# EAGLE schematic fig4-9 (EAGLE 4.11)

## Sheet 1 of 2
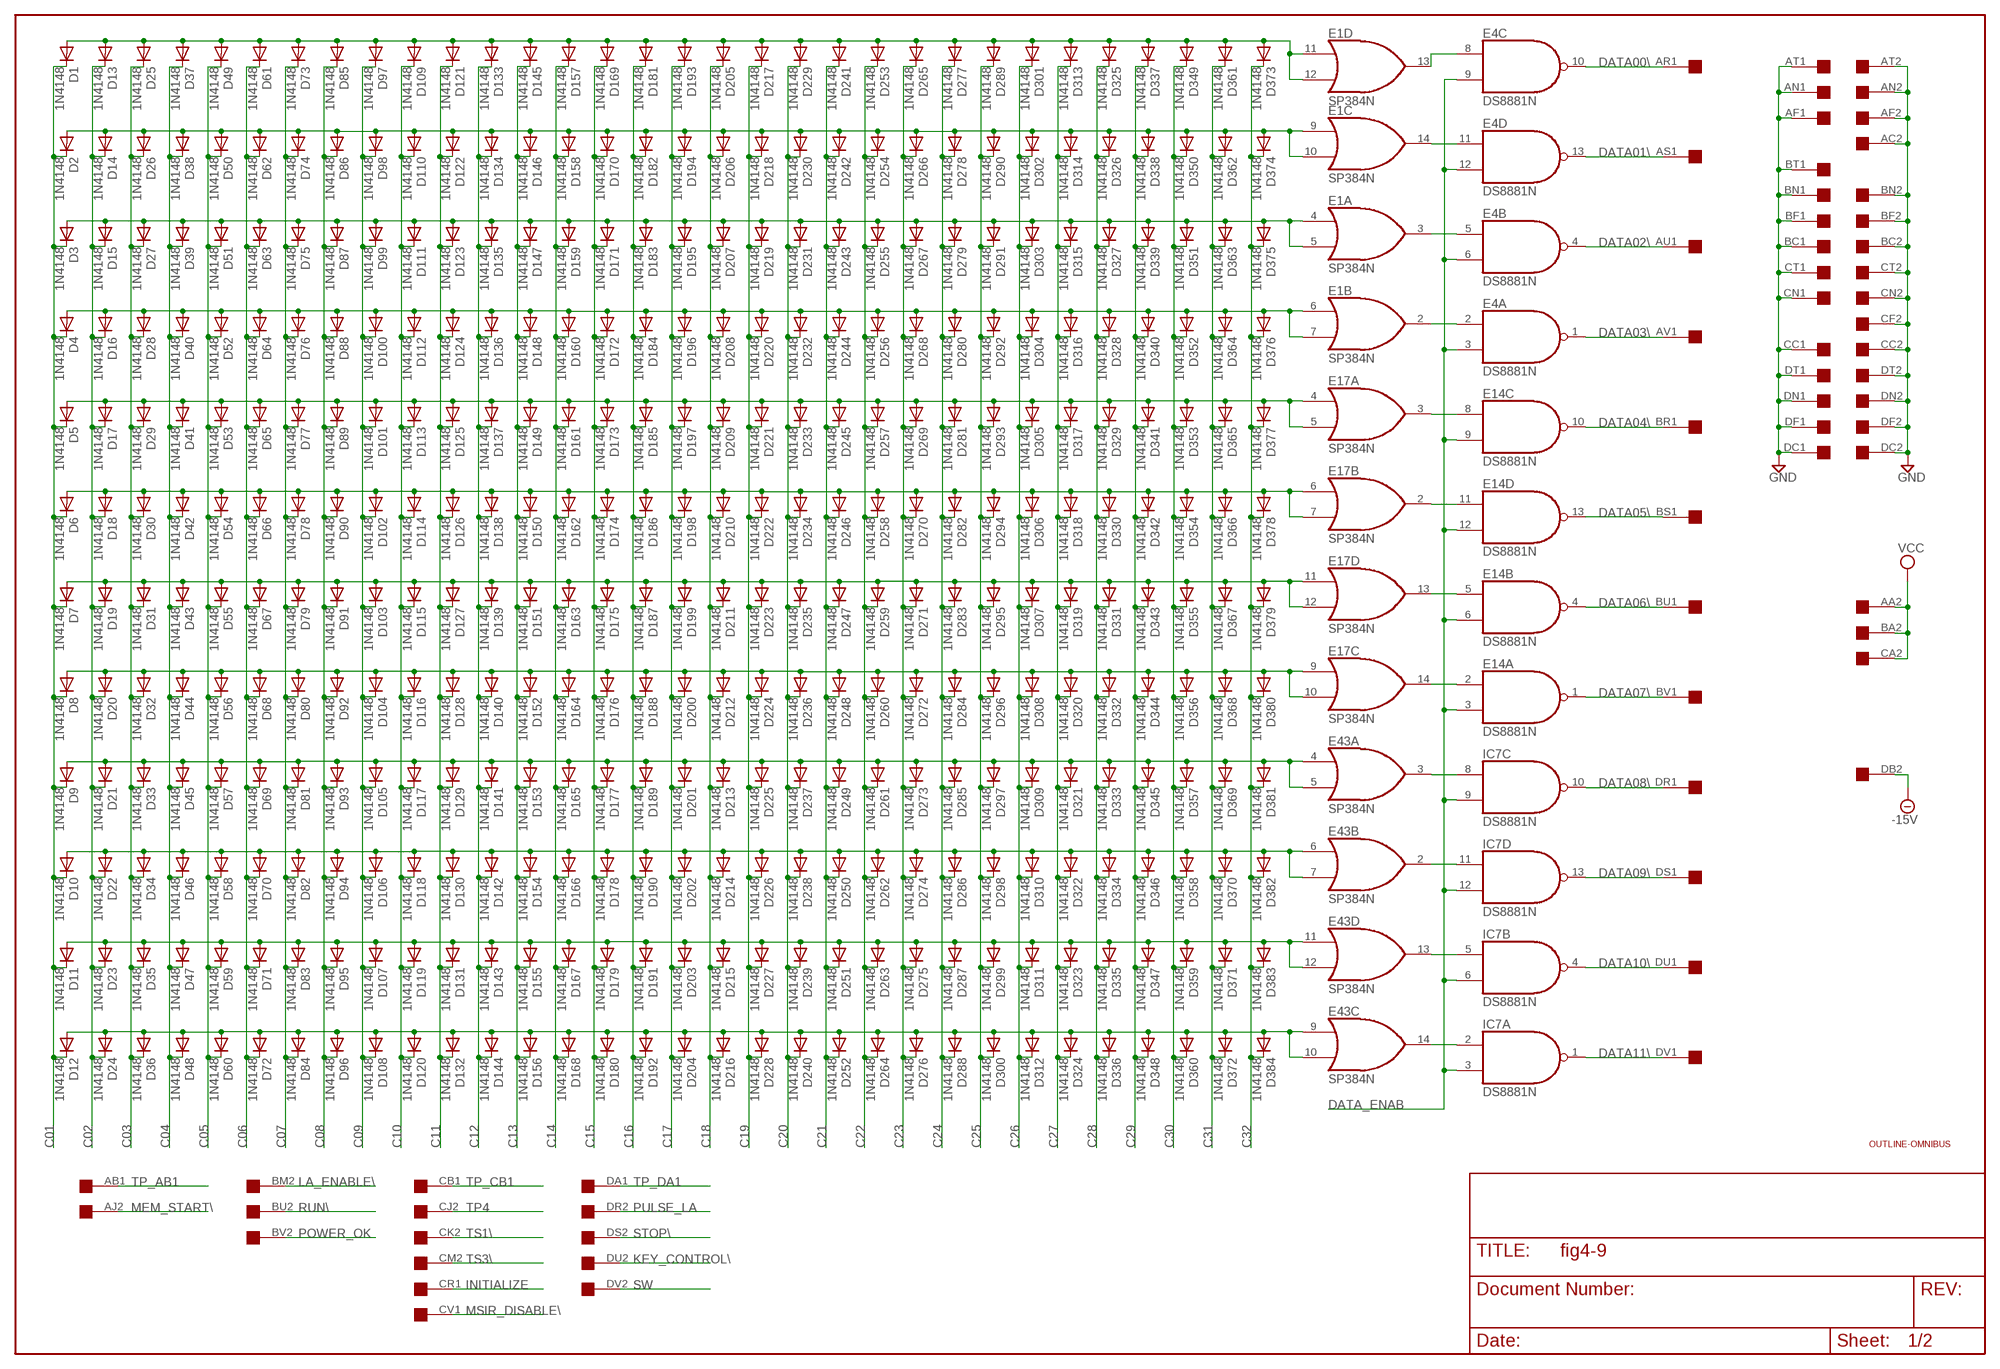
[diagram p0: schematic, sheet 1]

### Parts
D1  1N4148  [DO35-10]
D2  1N4148  [DO35-10]
D3  1N4148  [DO35-10]
D4  1N4148  [DO35-10]
D5  1N4148  [DO35-10]
D6  1N4148  [DO35-10]
D7  1N4148  [DO35-10]
D8  1N4148  [DO35-10]
D9  1N4148  [DO35-10]
D10  1N4148  [DO35-10]
D11  1N4148  [DO35-10]
D12  1N4148  [DO35-10]
D13  1N4148  [DO35-10]
D14  1N4148  [DO35-10]
D15  1N4148  [DO35-10]
D16  1N4148  [DO35-10]
D17  1N4148  [DO35-10]
D18  1N4148  [DO35-10]
D19  1N4148  [DO35-10]
D20  1N4148  [DO35-10]
D21  1N4148  [DO35-10]
D22  1N4148  [DO35-10]
D23  1N4148  [DO35-10]
D24  1N4148  [DO35-10]
D25  1N4148  [DO35-10]
D26  1N4148  [DO35-10]
D27  1N4148  [DO35-10]
D28  1N4148  [DO35-10]
D29  1N4148  [DO35-10]
D30  1N4148  [DO35-10]
D31  1N4148  [DO35-10]
D32  1N4148  [DO35-10]
D33  1N4148  [DO35-10]
D34  1N4148  [DO35-10]
D35  1N4148  [DO35-10]
D36  1N4148  [DO35-10]
D37  1N4148  [DO35-10]
D38  1N4148  [DO35-10]
D39  1N4148  [DO35-10]
D40  1N4148  [DO35-10]
D41  1N4148  [DO35-10]
D42  1N4148  [DO35-10]
D43  1N4148  [DO35-10]
D44  1N4148  [DO35-10]
D45  1N4148  [DO35-10]
D46  1N4148  [DO35-10]
D47  1N4148  [DO35-10]
D48  1N4148  [DO35-10]
D49  1N4148  [DO35-10]
D50  1N4148  [DO35-10]
D51  1N4148  [DO35-10]
D52  1N4148  [DO35-10]
D53  1N4148  [DO35-10]
D54  1N4148  [DO35-10]
D55  1N4148  [DO35-10]
D56  1N4148  [DO35-10]
D57  1N4148  [DO35-10]
D58  1N4148  [DO35-10]
D59  1N4148  [DO35-10]
D60  1N4148  [DO35-10]
D61  1N4148  [DO35-10]
D62  1N4148  [DO35-10]
D63  1N4148  [DO35-10]
D64  1N4148  [DO35-10]
D65  1N4148  [DO35-10]
D66  1N4148  [DO35-10]
D67  1N4148  [DO35-10]
D68  1N4148  [DO35-10]
D69  1N4148  [DO35-10]
D70  1N4148  [DO35-10]
D71  1N4148  [DO35-10]
D72  1N4148  [DO35-10]
D73  1N4148  [DO35-10]
D74  1N4148  [DO35-10]
D75  1N4148  [DO35-10]
D76  1N4148  [DO35-10]
D77  1N4148  [DO35-10]
D78  1N4148  [DO35-10]
D79  1N4148  [DO35-10]
D80  1N4148  [DO35-10]
D81  1N4148  [DO35-10]
D82  1N4148  [DO35-10]
D83  1N4148  [DO35-10]
D84  1N4148  [DO35-10]
D85  1N4148  [DO35-10]
D86  1N4148  [DO35-10]
D87  1N4148  [DO35-10]
D88  1N4148  [DO35-10]
D89  1N4148  [DO35-10]
D90  1N4148  [DO35-10]
D91  1N4148  [DO35-10]
D92  1N4148  [DO35-10]
D93  1N4148  [DO35-10]
D94  1N4148  [DO35-10]
D95  1N4148  [DO35-10]
D96  1N4148  [DO35-10]
D97  1N4148  [DO35-10]
D98  1N4148  [DO35-10]
D99  1N4148  [DO35-10]
D100  1N4148  [DO35-10]
D101  1N4148  [DO35-10]
D102  1N4148  [DO35-10]
D103  1N4148  [DO35-10]
D104  1N4148  [DO35-10]
D105  1N4148  [DO35-10]
D106  1N4148  [DO35-10]
D107  1N4148  [DO35-10]
D108  1N4148  [DO35-10]
D109  1N4148  [DO35-10]
D110  1N4148  [DO35-10]
D111  1N4148  [DO35-10]
D112  1N4148  [DO35-10]
D113  1N4148  [DO35-10]
D114  1N4148  [DO35-10]
D115  1N4148  [DO35-10]
D116  1N4148  [DO35-10]
D117  1N4148  [DO35-10]
D118  1N4148  [DO35-10]
D119  1N4148  [DO35-10]
D120  1N4148  [DO35-10]
D121  1N4148  [DO35-10]
D122  1N4148  [DO35-10]
D123  1N4148  [DO35-10]
D124  1N4148  [DO35-10]
D125  1N4148  [DO35-10]
D126  1N4148  [DO35-10]
D127  1N4148  [DO35-10]
D128  1N4148  [DO35-10]
D129  1N4148  [DO35-10]
D130  1N4148  [DO35-10]
D131  1N4148  [DO35-10]
D132  1N4148  [DO35-10]
D133  1N4148  [DO35-10]
D134  1N4148  [DO35-10]
D135  1N4148  [DO35-10]
D136  1N4148  [DO35-10]
D137  1N4148  [DO35-10]
D138  1N4148  [DO35-10]
D139  1N4148  [DO35-10]
D140  1N4148  [DO35-10]
D141  1N4148  [DO35-10]
D142  1N4148  [DO35-10]
D143  1N4148  [DO35-10]
D144  1N4148  [DO35-10]
D145  1N4148  [DO35-10]
D146  1N4148  [DO35-10]
D147  1N4148  [DO35-10]
D148  1N4148  [DO35-10]
D149  1N4148  [DO35-10]
D150  1N4148  [DO35-10]
D151  1N4148  [DO35-10]
D152  1N4148  [DO35-10]
D153  1N4148  [DO35-10]
D154  1N4148  [DO35-10]
D155  1N4148  [DO35-10]
D156  1N4148  [DO35-10]
D157  1N4148  [DO35-10]
D158  1N4148  [DO35-10]
D159  1N4148  [DO35-10]
D160  1N4148  [DO35-10]
D161  1N4148  [DO35-10]
D162  1N4148  [DO35-10]
D163  1N4148  [DO35-10]
D164  1N4148  [DO35-10]
D165  1N4148  [DO35-10]
D166  1N4148  [DO35-10]
D167  1N4148  [DO35-10]
D168  1N4148  [DO35-10]
D169  1N4148  [DO35-10]
D170  1N4148  [DO35-10]
D171  1N4148  [DO35-10]
D172  1N4148  [DO35-10]
D173  1N4148  [DO35-10]
D174  1N4148  [DO35-10]
D175  1N4148  [DO35-10]
D176  1N4148  [DO35-10]
D177  1N4148  [DO35-10]
D178  1N4148  [DO35-10]
D179  1N4148  [DO35-10]
D180  1N4148  [DO35-10]
D181  1N4148  [DO35-10]
D182  1N4148  [DO35-10]
D183  1N4148  [DO35-10]
D184  1N4148  [DO35-10]
D185  1N4148  [DO35-10]
D186  1N4148  [DO35-10]
D187  1N4148  [DO35-10]
D188  1N4148  [DO35-10]
D189  1N4148  [DO35-10]
D190  1N4148  [DO35-10]
D191  1N4148  [DO35-10]
D192  1N4148  [DO35-10]
D193  1N4148  [DO35-10]
D194  1N4148  [DO35-10]
D195  1N4148  [DO35-10]
D196  1N4148  [DO35-10]
D197  1N4148  [DO35-10]
D198  1N4148  [DO35-10]
D199  1N4148  [DO35-10]
D200  1N4148  [DO35-10]
D201  1N4148  [DO35-10]
D202  1N4148  [DO35-10]
D203  1N4148  [DO35-10]
D204  1N4148  [DO35-10]
D205  1N4148  [DO35-10]
D206  1N4148  [DO35-10]
D207  1N4148  [DO35-10]
D208  1N4148  [DO35-10]
D209  1N4148  [DO35-10]
D210  1N4148  [DO35-10]
D211  1N4148  [DO35-10]
D212  1N4148  [DO35-10]
D213  1N4148  [DO35-10]
D214  1N4148  [DO35-10]
D215  1N4148  [DO35-10]
D216  1N4148  [DO35-10]
D217  1N4148  [DO35-10]
D218  1N4148  [DO35-10]
D219  1N4148  [DO35-10]
D220  1N4148  [DO35-10]
D221  1N4148  [DO35-10]
D222  1N4148  [DO35-10]
D223  1N4148  [DO35-10]
D224  1N4148  [DO35-10]
D225  1N4148  [DO35-10]
D226  1N4148  [DO35-10]
D227  1N4148  [DO35-10]
D228  1N4148  [DO35-10]
D229  1N4148  [DO35-10]
D230  1N4148  [DO35-10]
D231  1N4148  [DO35-10]
D232  1N4148  [DO35-10]
D233  1N4148  [DO35-10]
D234  1N4148  [DO35-10]
D235  1N4148  [DO35-10]
D236  1N4148  [DO35-10]
D237  1N4148  [DO35-10]
D238  1N4148  [DO35-10]
D239  1N4148  [DO35-10]
D240  1N4148  [DO35-10]
D241  1N4148  [DO35-10]
D242  1N4148  [DO35-10]
D243  1N4148  [DO35-10]
D244  1N4148  [DO35-10]
D245  1N4148  [DO35-10]
D246  1N4148  [DO35-10]
D247  1N4148  [DO35-10]
D248  1N4148  [DO35-10]
D249  1N4148  [DO35-10]
D250  1N4148  [DO35-10]
D251  1N4148  [DO35-10]
D252  1N4148  [DO35-10]
D253  1N4148  [DO35-10]
D254  1N4148  [DO35-10]
D255  1N4148  [DO35-10]
D256  1N4148  [DO35-10]
D257  1N4148  [DO35-10]
D258  1N4148  [DO35-10]
D259  1N4148  [DO35-10]
D260  1N4148  [DO35-10]
D261  1N4148  [DO35-10]
D262  1N4148  [DO35-10]
D263  1N4148  [DO35-10]
D264  1N4148  [DO35-10]
D265  1N4148  [DO35-10]
D266  1N4148  [DO35-10]
D267  1N4148  [DO35-10]
D268  1N4148  [DO35-10]
D269  1N4148  [DO35-10]
D270  1N4148  [DO35-10]
D271  1N4148  [DO35-10]
D272  1N4148  [DO35-10]
D273  1N4148  [DO35-10]
D274  1N4148  [DO35-10]
D275  1N4148  [DO35-10]
D276  1N4148  [DO35-10]
D277  1N4148  [DO35-10]
D278  1N4148  [DO35-10]
D279  1N4148  [DO35-10]
D280  1N4148  [DO35-10]
D281  1N4148  [DO35-10]
D282  1N4148  [DO35-10]
D283  1N4148  [DO35-10]
D284  1N4148  [DO35-10]
D285  1N4148  [DO35-10]
D286  1N4148  [DO35-10]
D287  1N4148  [DO35-10]
D288  1N4148  [DO35-10]
D289  1N4148  [DO35-10]
D290  1N4148  [DO35-10]
D291  1N4148  [DO35-10]
D292  1N4148  [DO35-10]
D293  1N4148  [DO35-10]
D294  1N4148  [DO35-10]
D295  1N4148  [DO35-10]
D296  1N4148  [DO35-10]
D297  1N4148  [DO35-10]
D298  1N4148  [DO35-10]
D299  1N4148  [DO35-10]
D300  1N4148  [DO35-10]
D301  1N4148  [DO35-10]
D302  1N4148  [DO35-10]
D303  1N4148  [DO35-10]
D304  1N4148  [DO35-10]
D305  1N4148  [DO35-10]
D306  1N4148  [DO35-10]
D307  1N4148  [DO35-10]
D308  1N4148  [DO35-10]
D309  1N4148  [DO35-10]
D310  1N4148  [DO35-10]
D311  1N4148  [DO35-10]
D312  1N4148  [DO35-10]
D313  1N4148  [DO35-10]
D314  1N4148  [DO35-10]
D315  1N4148  [DO35-10]
D316  1N4148  [DO35-10]
D317  1N4148  [DO35-10]
D318  1N4148  [DO35-10]
D319  1N4148  [DO35-10]
D320  1N4148  [DO35-10]
D321  1N4148  [DO35-10]
D322  1N4148  [DO35-10]
D323  1N4148  [DO35-10]
D324  1N4148  [DO35-10]
D325  1N4148  [DO35-10]
D326  1N4148  [DO35-10]
D327  1N4148  [DO35-10]
D328  1N4148  [DO35-10]
D329  1N4148  [DO35-10]
D330  1N4148  [DO35-10]
D331  1N4148  [DO35-10]
D332  1N4148  [DO35-10]
D333  1N4148  [DO35-10]
D334  1N4148  [DO35-10]
D335  1N4148  [DO35-10]
D336  1N4148  [DO35-10]
D337  1N4148  [DO35-10]
D338  1N4148  [DO35-10]
D339  1N4148  [DO35-10]
D340  1N4148  [DO35-10]
D341  1N4148  [DO35-10]
D342  1N4148  [DO35-10]
D343  1N4148  [DO35-10]
D344  1N4148  [DO35-10]
D345  1N4148  [DO35-10]
D346  1N4148  [DO35-10]
D347  1N4148  [DO35-10]
D348  1N4148  [DO35-10]
D349  1N4148  [DO35-10]
D350  1N4148  [DO35-10]
D351  1N4148  [DO35-10]
D352  1N4148  [DO35-10]
D353  1N4148  [DO35-10]
D354  1N4148  [DO35-10]
D355  1N4148  [DO35-10]
D356  1N4148  [DO35-10]
D357  1N4148  [DO35-10]
D358  1N4148  [DO35-10]
D359  1N4148  [DO35-10]
D360  1N4148  [DO35-10]
D361  1N4148  [DO35-10]
D362  1N4148  [DO35-10]
D363  1N4148  [DO35-10]
D364  1N4148  [DO35-10]
D365  1N4148  [DO35-10]
D366  1N4148  [DO35-10]
D367  1N4148  [DO35-10]
D368  1N4148  [DO35-10]
D369  1N4148  [DO35-10]
D370  1N4148  [DO35-10]
D371  1N4148  [DO35-10]
D372  1N4148  [DO35-10]
D373  1N4148  [DO35-10]
D374  1N4148  [DO35-10]
D375  1N4148  [DO35-10]
D376  1N4148  [DO35-10]
D377  1N4148  [DO35-10]
D378  1N4148  [DO35-10]
D379  1N4148  [DO35-10]
D380  1N4148  [DO35-10]
D381  1N4148  [DO35-10]
D382  1N4148  [DO35-10]
D383  1N4148  [DO35-10]
D384  1N4148  [DO35-10]
E1  SP384N  [DIL14]
E4  DS8881N  [DIL14]
E14  DS8881N  [DIL14]
E17  SP384N  [DIL14]
E43  SP384N  [DIL14]
IC7  DS8881N  [DIL14]
U$1  OUTLINE-OMNIBUS  [OMNIBUS]
U$2  QUAD  [EDGE-CON8]

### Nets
-15V: U$2.DB2
C01: D1.C D2.C D3.C D4.C D5.C D6.C D7.C D8.C D9.C D10.C D11.C D12.C ; also sheet 2
C02: D13.C D14.C D15.C D16.C D17.C D18.C D19.C D20.C D21.C D22.C D23.C D24.C ; also sheet 2
C03: D25.C D26.C D27.C D28.C D29.C D30.C D31.C D32.C D33.C D34.C D35.C D36.C ; also sheet 2
C04: D37.C D38.C D39.C D40.C D41.C D42.C D43.C D44.C D45.C D46.C D47.C D48.C ; also sheet 2
C05: D49.C D50.C D51.C D52.C D53.C D54.C D55.C D56.C D57.C D58.C D59.C D60.C ; also sheet 2
C06: D61.C D62.C D63.C D64.C D65.C D66.C D67.C D68.C D69.C D70.C D71.C D72.C ; also sheet 2
C07: D73.C D74.C D75.C D76.C D77.C D78.C D79.C D80.C D81.C D82.C D83.C D84.C ; also sheet 2
C08: D85.C D86.C D87.C D88.C D89.C D90.C D91.C D92.C D93.C D94.C D95.C D96.C ; also sheet 2
C09: D97.C D98.C D99.C D100.C D101.C D102.C D103.C D104.C D105.C D106.C D107.C D108.C ; also sheet 2
C10: D109.C D110.C D111.C D112.C D113.C D114.C D115.C D116.C D117.C D118.C D119.C D120.C ; also sheet 2
C11: D121.C D122.C D123.C D124.C D125.C D126.C D127.C D128.C D129.C D130.C D131.C D132.C ; also sheet 2
C12: D133.C D134.C D135.C D136.C D137.C D138.C D139.C D140.C D141.C D142.C D143.C D144.C ; also sheet 2
C13: D145.C D146.C D147.C D148.C D149.C D150.C D151.C D152.C D153.C D154.C D155.C D156.C ; also sheet 2
C14: D157.C D158.C D159.C D160.C D161.C D162.C D163.C D164.C D165.C D166.C D167.C D168.C ; also sheet 2
C15: D169.C D170.C D171.C D172.C D173.C D174.C D175.C D176.C D177.C D178.C D179.C D180.C ; also sheet 2
C16: D181.C D182.C D183.C D184.C D185.C D186.C D187.C D188.C D189.C D190.C D191.C D192.C ; also sheet 2
C17: D193.C D194.C D195.C D196.C D197.C D198.C D199.C D200.C D201.C D202.C D203.C D204.C ; also sheet 2
C18: D205.C D206.C D207.C D208.C D209.C D210.C D211.C D212.C D213.C D214.C D215.C D216.C ; also sheet 2
C19: D217.C D218.C D219.C D220.C D221.C D222.C D223.C D224.C D225.C D226.C D227.C D228.C ; also sheet 2
C20: D229.C D230.C D231.C D232.C D233.C D234.C D235.C D236.C D237.C D238.C D239.C D240.C ; also sheet 2
C21: D241.C D242.C D243.C D244.C D245.C D246.C D247.C D248.C D249.C D250.C D251.C D252.C ; also sheet 2
C22: D253.C D254.C D255.C D256.C D257.C D258.C D259.C D260.C D261.C D262.C D263.C D264.C ; also sheet 2
C23: D265.C D266.C D267.C D268.C D269.C D270.C D271.C D272.C D273.C D274.C D275.C D276.C ; also sheet 2
C24: D277.C D278.C D279.C D280.C D281.C D282.C D283.C D284.C D285.C D286.C D287.C D288.C ; also sheet 2
C25: D289.C D290.C D291.C D292.C D293.C D294.C D295.C D296.C D297.C D298.C D299.C D300.C ; also sheet 2
C26: D301.C D302.C D303.C D304.C D305.C D306.C D307.C D308.C D309.C D310.C D311.C D312.C ; also sheet 2
C27: D313.C D314.C D315.C D316.C D317.C D318.C D319.C D320.C D321.C D322.C D323.C D324.C ; also sheet 2
C28: D325.C D326.C D327.C D328.C D329.C D330.C D331.C D332.C D333.C D334.C D335.C D336.C ; also sheet 2
C29: D337.C D338.C D339.C D340.C D341.C D342.C D343.C D344.C D345.C D346.C D347.C D348.C ; also sheet 2
C30: D349.C D350.C D351.C D352.C D353.C D354.C D355.C D356.C D357.C D358.C D359.C D360.C ; also sheet 2
C31: D361.C D362.C D363.C D364.C D365.C D366.C D367.C D368.C D369.C D370.C D371.C D372.C ; also sheet 2
C32: D373.C D374.C D375.C D376.C D377.C D378.C D379.C D380.C D381.C D382.C D383.C D384.C ; also sheet 2
DATA00\: E4.10(C:O) U$2.AR1
DATA01\: E4.13(D:O) U$2.AS1
DATA02\: E4.4(B:O) U$2.AU1
DATA03\: E4.1(A:O) U$2.AV1
DATA04\: E14.10(C:O) U$2.BR1
DATA05\: E14.13(D:O) U$2.BS1
DATA06\: E14.4(B:O) U$2.BU1
DATA07\: E14.1(A:O) U$2.BV1
DATA08\: IC7.10(C:O) U$2.DR1
DATA09\: IC7.13(D:O) U$2.DS1
DATA10\: IC7.4(B:O) U$2.DU1
DATA11\: IC7.1(A:O) U$2.DV1
DATA_ENAB: E4.3(A:I1) E4.6(B:I1) E4.9(C:I1) E4.12(D:I1) E14.3(A:I1) E14.6(B:I1) E14.9(C:I1) E14.12(D:I1) IC7.3(A:I1) IC7.6(B:I1) IC7.9(C:I1) IC7.12(D:I1)
GND: U$2.AC2 U$2.AF1 U$2.AF2 U$2.AN1 U$2.AN2 U$2.AT1 U$2.AT2 U$2.BC1 U$2.BC2 U$2.BF1 U$2.BF2 U$2.BN1 U$2.BN2 U$2.BT1 U$2.CC1 U$2.CC2 U$2.CF2 U$2.CN1 U$2.CN2 U$2.CT1 U$2.CT2 U$2.DC1 U$2.DC2 U$2.DF1 U$2.DF2 U$2.DN1 U$2.DN2 U$2.DT1 U$2.DT2 ; also sheet 2
INITIALIZE: U$2.CR1
KEY_CONTROL\: U$2.DU2
LA_ENABLE\: U$2.BM2
MEM_START\: U$2.AJ2
MSIR_DISABLE\: U$2.CV1
N$33: D1.A D13.A D25.A D37.A D49.A D61.A D73.A D85.A D97.A D109.A D121.A D133.A D145.A D157.A D169.A D181.A D193.A D205.A D217.A D229.A D241.A D253.A D265.A D277.A D289.A D301.A D313.A D325.A D337.A D349.A D361.A D373.A E1.11(D:I0) E1.12(D:I1)
N$34: D12.A D24.A D36.A D48.A D60.A D72.A D84.A D96.A D108.A D120.A D132.A D144.A D156.A D168.A D180.A D192.A D204.A D216.A D228.A D240.A D252.A D264.A D276.A D288.A D300.A D312.A D324.A D336.A D348.A D360.A D372.A D384.A E43.9(C:I0) E43.10(C:I1)
N$35: D11.A D23.A D35.A D47.A D59.A D71.A D83.A D95.A D107.A D119.A D131.A D143.A D155.A D167.A D179.A D191.A D203.A D215.A D227.A D239.A D251.A D263.A D275.A D287.A D299.A D311.A D323.A D335.A D347.A D359.A D371.A D383.A E43.11(D:I0) E43.12(D:I1)
N$36: D10.A D22.A D34.A D46.A D58.A D70.A D82.A D94.A D106.A D118.A D130.A D142.A D154.A D166.A D178.A D190.A D202.A D214.A D226.A D238.A D250.A D262.A D274.A D286.A D298.A D310.A D322.A D334.A D346.A D358.A D370.A D382.A E43.6(B:I0) E43.7(B:I1)
N$37: D8.A D20.A D32.A D44.A D56.A D68.A D80.A D92.A D104.A D116.A D128.A D140.A D152.A D164.A D176.A D188.A D200.A D212.A D224.A D236.A D248.A D260.A D272.A D284.A D296.A D308.A D320.A D332.A D344.A D356.A D368.A D380.A E17.9(C:I0) E17.10(C:I1)
N$38: D7.A D19.A D31.A D43.A D55.A D67.A D79.A D91.A D103.A D115.A D127.A D139.A D151.A D163.A D175.A D187.A D199.A D211.A D223.A D235.A D247.A D259.A D271.A D283.A D295.A D307.A D319.A D331.A D343.A D355.A D367.A D379.A E17.11(D:I0) E17.12(D:I1)
N$39: D9.A D21.A D33.A D45.A D57.A D69.A D81.A D93.A D105.A D117.A D129.A D141.A D153.A D165.A D177.A D189.A D201.A D213.A D225.A D237.A D249.A D261.A D273.A D285.A D297.A D309.A D321.A D333.A D345.A D357.A D369.A D381.A E43.4(A:I0) E43.5(A:I1)
N$40: D6.A D18.A D30.A D42.A D54.A D66.A D78.A D90.A D102.A D114.A D126.A D138.A D150.A D162.A D174.A D186.A D198.A D210.A D222.A D234.A D246.A D258.A D270.A D282.A D294.A D306.A D318.A D330.A D342.A D354.A D366.A D378.A E17.6(B:I0) E17.7(B:I1)
N$41: D5.A D17.A D29.A D41.A D53.A D65.A D77.A D89.A D101.A D113.A D125.A D137.A D149.A D161.A D173.A D185.A D197.A D209.A D221.A D233.A D245.A D257.A D269.A D281.A D293.A D305.A D317.A D329.A D341.A D353.A D365.A D377.A E17.4(A:I0) E17.5(A:I1)
N$42: D4.A D16.A D28.A D40.A D52.A D64.A D76.A D88.A D100.A D112.A D124.A D136.A D148.A D160.A D172.A D184.A D196.A D208.A D220.A D232.A D244.A D256.A D268.A D280.A D292.A D304.A D316.A D328.A D340.A D352.A D364.A D376.A E1.6(B:I0) E1.7(B:I1)
N$43: D3.A D15.A D27.A D39.A D51.A D63.A D75.A D87.A D99.A D111.A D123.A D135.A D147.A D159.A D171.A D183.A D195.A D207.A D219.A D231.A D243.A D255.A D267.A D279.A D291.A D303.A D315.A D327.A D339.A D351.A D363.A D375.A E1.4(A:I0) E1.5(A:I1)
N$44: D2.A D14.A D26.A D38.A D50.A D62.A D74.A D86.A D98.A D110.A D122.A D134.A D146.A D158.A D170.A D182.A D194.A D206.A D218.A D230.A D242.A D254.A D266.A D278.A D290.A D302.A D314.A D326.A D338.A D350.A D362.A D374.A E1.9(C:I0) E1.10(C:I1)
N$45: E14.5(B:I0) E17.13(D:O)
N$46: E14.11(D:I0) E17.2(B:O)
N$47: E14.8(C:I0) E17.3(A:O)
N$48: E1.2(B:O) E4.2(A:I0)
N$49: E1.3(A:O) E4.5(B:I0)
N$50: E1.14(C:O) E4.11(D:I0)
N$51: E1.13(D:O) E4.8(C:I0)
N$52: E43.14(C:O) IC7.2(A:I0)
N$53: E43.13(D:O) IC7.5(B:I0)
N$54: E43.2(B:O) IC7.11(D:I0)
N$55: E43.3(A:O) IC7.8(C:I0)
N$56: E14.2(A:I0) E17.14(C:O)
POWER_OK: U$2.BV2
PULSE_LA: U$2.DR2
RUN\: U$2.BU2
STOP\: U$2.DS2
SW: U$2.DV2
TP4: U$2.CJ2
TP_AB1: U$2.AB1
TP_CB1: U$2.CB1
TP_DA1: U$2.DA1
TS1\: U$2.CK2 ; also sheet 2
TS3\: U$2.CM2
VCC: U$2.AA2 U$2.BA2 U$2.CA2
Unconnected: U$2.AA1 U$2.AB2 U$2.AC1 U$2.AD1 U$2.AD2 U$2.AE1 U$2.AE2 U$2.AH1 U$2.AH2 U$2.AJ1 U$2.AK1 U$2.AK2 U$2.AL1 U$2.AL2 U$2.AM1 U$2.AM2 U$2.AP1 U$2.AP2 U$2.AR2 U$2.AS2 U$2.AU2 U$2.AV2 U$2.BA1 U$2.BB1 U$2.BB2 U$2.BD1 U$2.BD2 U$2.BE1 U$2.BE2 U$2.BH1 U$2.BH2 U$2.BJ1 U$2.BJ2 U$2.BK1 U$2.BK2 U$2.BL1 U$2.BL2 U$2.BM1 U$2.BP1 U$2.BP2 U$2.BR2 U$2.BS2 U$2.BT2 U$2.CA1 U$2.CB2 U$2.CD1 U$2.CD2 U$2.CE1 U$2.CE2 U$2.CF1 U$2.CH1 U$2.CH2 U$2.CJ1 U$2.CK1 U$2.CL1 U$2.CL2 U$2.CM1 U$2.CP1 U$2.CP2 U$2.CR2 U$2.CS1 U$2.CS2 U$2.CU1 U$2.CU2 U$2.CV2 U$2.DA2 U$2.DB1 U$2.DD1 U$2.DD2 U$2.DE1 U$2.DE2 U$2.DH1 U$2.DH2 U$2.DJ1 U$2.DJ2 U$2.DK1 U$2.DK2 U$2.DL1 U$2.DL2 U$2.DM1 U$2.DM2 U$2.DP1 U$2.DP2

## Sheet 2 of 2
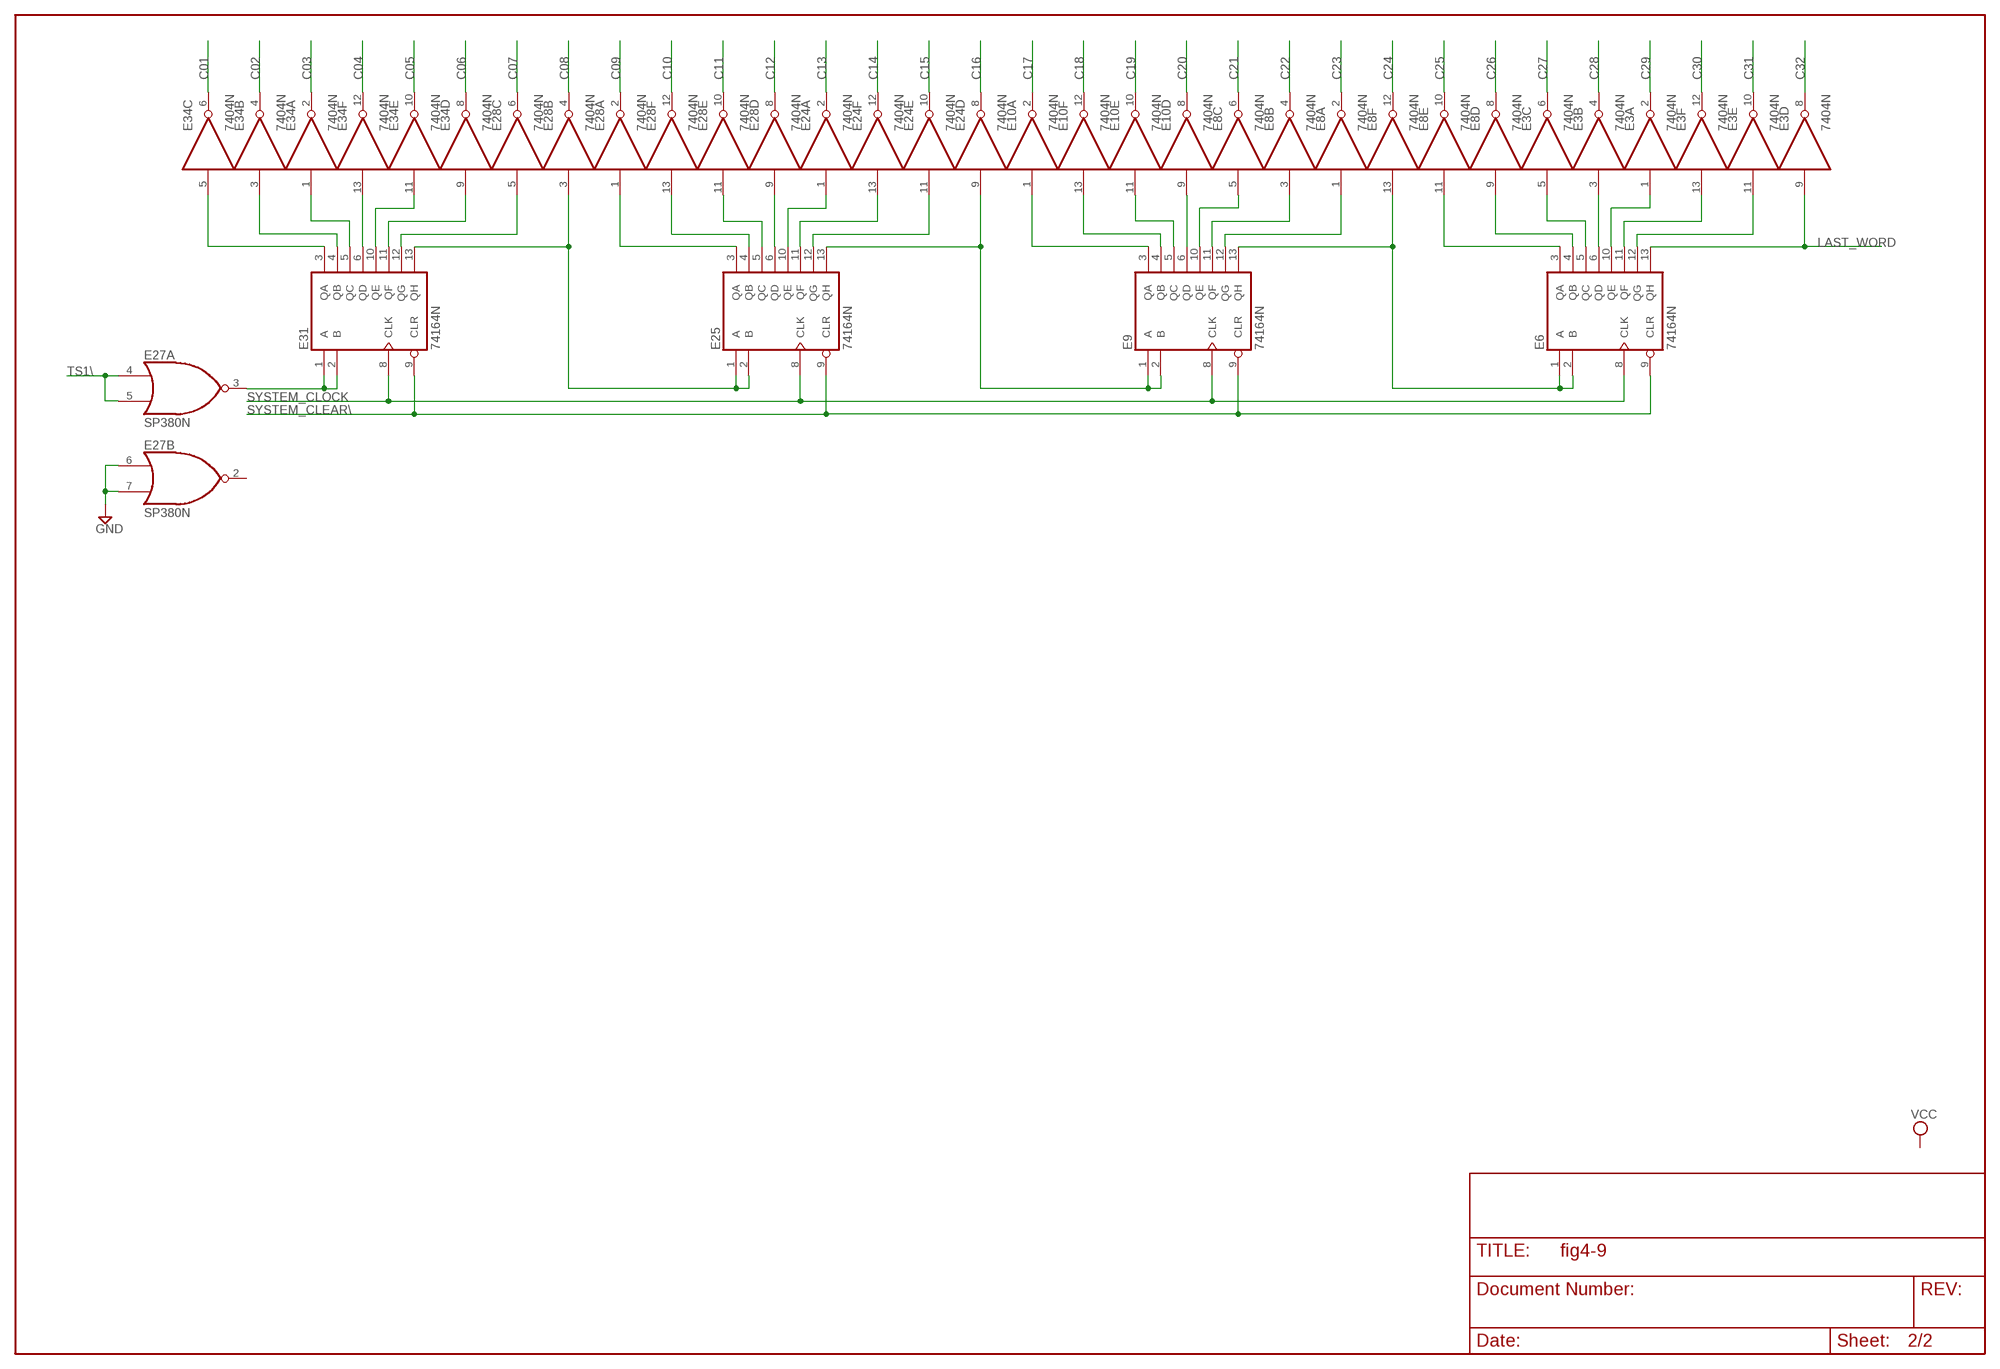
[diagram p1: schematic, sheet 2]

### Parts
E3  7404N  [DIL14]
E6  74164N  [DIL14]
E8  7404N  [DIL14]
E9  74164N  [DIL14]
E10  7404N  [DIL14]
E24  7404N  [DIL14]
E25  74164N  [DIL14]
E27  SP380N  [DIL14]
E28  7404N  [DIL14]
E31  74164N  [DIL14]
E34  7404N  [DIL14]

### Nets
C01: E34.6(C:O) ; also sheet 1
C02: E34.4(B:O) ; also sheet 1
C03: E34.2(A:O) ; also sheet 1
C04: E34.12(F:O) ; also sheet 1
C05: E34.10(E:O) ; also sheet 1
C06: E34.8(D:O) ; also sheet 1
C07: E28.6(C:O) ; also sheet 1
C08: E28.4(B:O) ; also sheet 1
C09: E28.2(A:O) ; also sheet 1
C10: E28.12(F:O) ; also sheet 1
C11: E28.10(E:O) ; also sheet 1
C12: E28.8(D:O) ; also sheet 1
C13: E24.2(A:O) ; also sheet 1
C14: E24.12(F:O) ; also sheet 1
C15: E24.10(E:O) ; also sheet 1
C16: E24.8(D:O) ; also sheet 1
C17: E10.2(A:O) ; also sheet 1
C18: E10.12(F:O) ; also sheet 1
C19: E10.10(E:O) ; also sheet 1
C20: E10.8(D:O) ; also sheet 1
C21: E8.6(C:O) ; also sheet 1
C22: E8.4(B:O) ; also sheet 1
C23: E8.2(A:O) ; also sheet 1
C24: E8.12(F:O) ; also sheet 1
C25: E8.10(E:O) ; also sheet 1
C26: E8.8(D:O) ; also sheet 1
C27: E3.6(C:O) ; also sheet 1
C28: E3.4(B:O) ; also sheet 1
C29: E3.2(A:O) ; also sheet 1
C30: E3.12(F:O) ; also sheet 1
C31: E3.10(E:O) ; also sheet 1
C32: E3.8(D:O) ; also sheet 1
GND: E27.6(B:I0) E27.7(B:I1) ; also sheet 1
LAST_WORD: E3.9(D:I) E6.13(QH)
N$1: E27.3(A:O) E31.1(A) E31.2(B)
N$32: E31.3(QA) E34.5(C:I)
N$69: E31.6(QD) E34.13(F:I)
N$70: E9.5(QC) E10.11(E:I)
N$71: E9.6(QD) E10.9(D:I)
N$72: E3.3(B:I) E6.6(QD)
N$73: E31.4(QB) E34.3(B:I)
N$74: E31.5(QC) E34.1(A:I)
N$75: E31.10(QE) E34.11(E:I)
N$76: E31.11(QF) E34.9(D:I)
N$77: E28.5(C:I) E31.12(QG)
N$78: E25.3(QA) E28.1(A:I)
N$79: E25.4(QB) E28.13(F:I)
N$80: E25.5(QC) E28.11(E:I)
N$81: E25.6(QD) E28.9(D:I)
N$82: E24.1(A:I) E25.10(QE)
N$83: E9.3(QA) E10.1(A:I)
N$84: E6.3(QA) E8.11(E:I)
N$85: E3.11(E:I) E6.12(QG)
N$86: E3.13(F:I) E6.11(QF)
N$87: E3.1(A:I) E6.10(QE)
N$88: E24.13(F:I) E25.11(QF)
N$89: E24.11(E:I) E25.12(QG)
N$90: E9.4(QB) E10.13(F:I)
N$91: E8.5(C:I) E9.10(QE)
N$92: E8.3(B:I) E9.11(QF)
N$93: E8.1(A:I) E9.12(QG)
N$94: E6.4(QB) E8.9(D:I)
N$95: E3.5(C:I) E6.5(QC)
N$96: E6.1(A) E6.2(B) E8.13(F:I) E9.13(QH)
N$97: E9.1(A) E9.2(B) E24.9(D:I) E25.13(QH)
N$98: E25.1(A) E25.2(B) E28.3(B:I) E31.13(QH)
SYSTEM_CLEAR\: E6.9(CLR) E9.9(CLR) E25.9(CLR) E31.9(CLR)
SYSTEM_CLOCK: E6.8(CLK) E9.8(CLK) E25.8(CLK) E31.8(CLK)
TS1\: E27.4(A:I0) E27.5(A:I1) ; also sheet 1
Unconnected: E10.3(B:I) E10.4(B:O) E10.5(C:I) E10.6(C:O) E24.3(B:I) E24.4(B:O) E24.5(C:I) E24.6(C:O) E27.2(B:O) E27.9(C:I0) E27.10(C:I1) E27.11(D:I0) E27.12(D:I1) E27.13(D:O) E27.14(C:O)

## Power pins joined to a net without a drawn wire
GND: E1.1(GND) E3.7(P:GND) E4.7(P:GND) E6.7(GND) E8.7(P:GND) E9.7(GND) E10.7(P:GND) E14.7(P:GND) E17.1(GND) E24.7(P:GND) E25.7(GND) E27.1(P:GND) E28.7(P:GND) E31.7(GND) E34.7(P:GND) E43.1(GND) IC7.7(P:GND)
VCC: E1.8(VCC) E3.14(P:VCC) E4.14(P:VCC) E6.14(VCC) E8.14(P:VCC) E9.14(VCC) E10.14(P:VCC) E14.14(P:VCC) E17.8(VCC) E24.14(P:VCC) E25.14(VCC) E27.8(P:VCC) E28.14(P:VCC) E31.14(VCC) E34.14(P:VCC) E43.8(VCC) IC7.14(P:VCC)

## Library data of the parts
D1-D384 = diode:1N4148: DIODE
E1 E17 E43 = dec-con:SP384: Quad OR gate
E3 E8 E10 E24 E28 E34 = 74xx-jameco:74*04: Hex INVERTER
E4 E14 IC7 = dec-con:DS8881: Quad 2-input NAND gate, open collector
E6 E9 E25 E31 = 74xx-jameco:74*164: 8-bit parallel out SHIFT REGISTER
E27 = dec-con:SP380: Quad NOR gate (use 8640)
U$1 = dec-con:OUTLINE-*: Board outlines for DEC boards.
U$2 = dec-con:QUAD: Quad-Height DEC board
